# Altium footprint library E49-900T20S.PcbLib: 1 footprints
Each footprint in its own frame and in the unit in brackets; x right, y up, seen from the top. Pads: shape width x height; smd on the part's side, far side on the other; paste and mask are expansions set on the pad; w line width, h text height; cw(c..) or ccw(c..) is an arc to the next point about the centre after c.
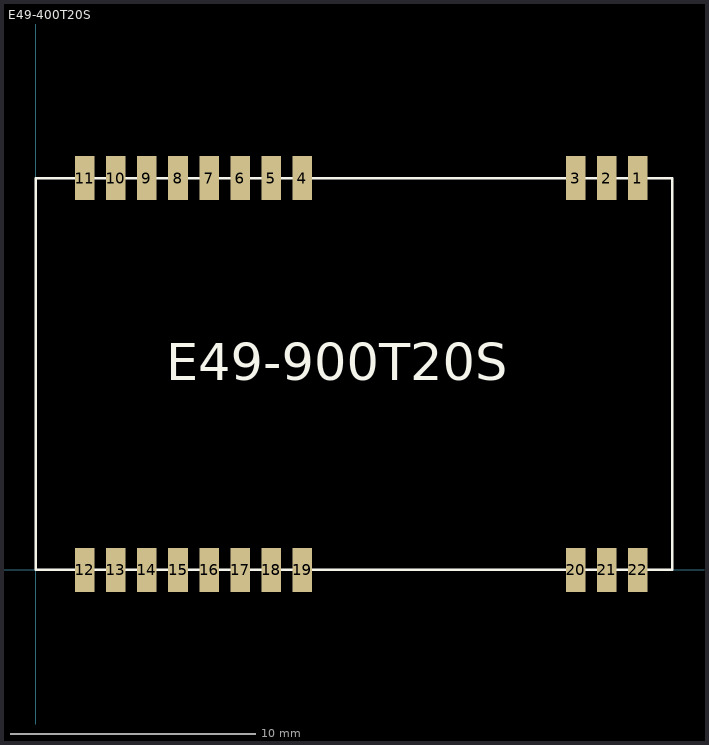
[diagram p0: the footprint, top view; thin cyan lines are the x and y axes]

## E49-400T20S [mm]
pads (22):
  rect 0.8x1.8 smd: 1(24.6,16) 2(23.33,16) 3(22.06,16) 4(10.89,16) 5(9.62,16) 6(8.35,16) 7(7.08,16) 8(5.81,16) 9(4.54,16) 10(3.27,16) 11(2,16) 12(2,0) 13(3.27,0) 14(4.54,0) 15(5.81,0) 16(7.08,0) 17(8.35,0) 18(9.62,0) 19(10.89,0) 20(22.06,0) 21(23.33,0) 22(24.6,0)
Top Overlay:
  lines w0.1: 0,0 0,16 26,16 26,0 0,0
  text "E49-900T20S" at 5.334,7.747 h1.52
